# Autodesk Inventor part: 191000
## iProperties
Shininess: 64.0
Length Units: 11272
Angle Units: 11279
Time Units: 11290
Mass Units: 11286
Length Display Precision: 3
Angle Display Precision: 2
Compacted: True
Part Number: 191000
Document SubType Name: Modeling
Created: 2004-06
Designer: jpittman
Manufacturer: Standard
Standards Organization: Custom
Density: 0.0
Volumn: 0.0
Area: 0.0
PropertySet Name: Model Information
Control State: 0
Master: False
Checked Out: False
Author: jpittman
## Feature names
1. Extrusion1
